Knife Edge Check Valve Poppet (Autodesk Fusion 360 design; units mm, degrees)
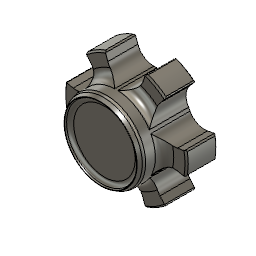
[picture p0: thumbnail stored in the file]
sketch "Sketch1" plane through (0, 0, 0) normal (1, 0, 0) x axis (0, 0, -1)
  line L1 (-19.05, 0) -> (0, 0)
  line L2 (-4.9004, 3.81) -> (-2.9273, 3.81)
  line L3 (-5.3403, 3.556) -> (-4.9004, 3.81)
  line L4 (-2.9274, 5.9563) -> (-2.9273, 3.81)
  line L5 (0, 5.9563) -> (-2.9274, 5.9563)
  line L6 (0, 0) -> (0, 5.9563)
  line L7 (-5.3403, 3.5052) -> (-5.3403, 3.556)
  line L8 (-4.9593, 3.2852) -> (-5.3403, 3.5052)
  line L9 (-4.9593, 0) -> (-4.9593, 3.2852)
  point P1 (0, 0)
  point P2 (0, 0)
  point P9 (0, 0)
  point P12 (-4.9593, 0)
  point P6 (-5.3403, 3.556)
  point P10 (-5.3403, 3.5052)
  coincident P1 P2
  horizontal L1
  parallel L1 L2
  perpendicular L2 L4
  coincident P1 P9
  perpendicular L1 L6
  perpendicular L2 L7
  coincident L1 P12
  perpendicular L1 L9
  dimension "d1" = 7.62
  dimension "d5" angle L2 L3 = 30
  dimension "d6" = 11.9126
  dimension "d7" distance P6 L4 = 2.413 (= "0.11 in - 0.015 in")
  dimension "d8" distance P6 L6 = 5.3403 (= "0.26025 in - 0.03 in - 0.02 in")
  dimension "d21" distance P6 P10 = 0.0508
  dimension "d22" angle L7 L8 = 120
  dimension "d29" distance L7 L9 = 0.381
  dimension "d30" = 7.112
revolve "Revolve1" sketch "Sketch1" AlongAngle 360
chamfer "Chamfer1" distance 0.0762 distance 0.1524
sketch "Sketch2" plane through (0, 0, 0) normal (0, 0, -1) x axis (-1, 0, 0)
  line L1 (0, 6.35) -> (0, 0)
  line L2 (2.2225, 6.35) -> (0, 6.35)
  line L3 (0, 0) -> (2.2225, 6.35)
  line L4 (-2.2225, 6.35) -> (0, 6.35)
  line L5 (0, 0) -> (-2.2225, 6.35)
  line L6 (0, 0) -> (-6.6105, 1.2503)
  line L7 (-6.6105, 1.2503) -> (-5.4993, 3.175)
  line L8 (-4.388, 5.0997) -> (-5.4993, 3.175)
  line L9 (0, 0) -> (-4.388, 5.0997)
  line L10 (0, 0) -> (-4.388, -5.0997)
  line L11 (-4.388, -5.0997) -> (-5.4993, -3.175)
  line L12 (-6.6105, -1.2503) -> (-5.4993, -3.175)
  line L13 (0, 0) -> (-6.6105, -1.2503)
  line L14 (0, 0) -> (2.2225, -6.35)
  line L15 (2.2225, -6.35) -> (0, -6.35)
  line L16 (-2.2225, -6.35) -> (0, -6.35)
  line L17 (0, 0) -> (-2.2225, -6.35)
  line L18 (0, 0) -> (6.6105, -1.2503)
  line L19 (6.6105, -1.2503) -> (5.4993, -3.175)
  line L20 (4.388, -5.0997) -> (5.4993, -3.175)
  line L21 (0, 0) -> (4.388, -5.0997)
  line L22 (0, 0) -> (4.388, 5.0997)
  line L23 (4.388, 5.0997) -> (5.4993, 3.175)
  line L24 (6.6105, 1.2503) -> (5.4993, 3.175)
  line L25 (0, 0) -> (6.6105, 1.2503)
  circle C1 centre (0, 0) radius 3.81
  circle C2 centre (0, 0) radius 5.8801
  point P1 (0, 0)
  point P2 (0, 0)
  point P3 (0, 0)
  point P6 (0, 0)
  point P8 (0, 0)
  point P20 (0, 0)
  point P34 (0, 0)
  point P5 (2.2225, 6.35)
  point P7 (-2.2225, 6.35)
  point P4 (0, 6.35)
  coincident P1 P2
  coincident P1 P3
  vertical L1
  perpendicular L1 L2
  coincident P2 P6
  perpendicular L1 L4
  coincident P2 P8
  equal L2 L4
  coincident P20 P34
  dimension "d10" distance P5 P7 = 4.445
  dimension "d13" distance P3 P4 = 6.35
  dimension "d14" diameter C1 = 7.62
  dimension "d12" C-Pattern1-Angle = 360
extrude "Extrude1" cut sketch "Sketch2" profile of L3 L5 L6 L9 L10 L13 L14 L17 L18 L21 L22 L25 C1 against normal blind 7.112
fillet "Fillet1" radius 1.5875
fillet "Fillet3" radius 0.889
fillet "Fillet4" radius 0.508
fillet "Fillet5" radius 0.508
fillet "Fillet8" radius 0.127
